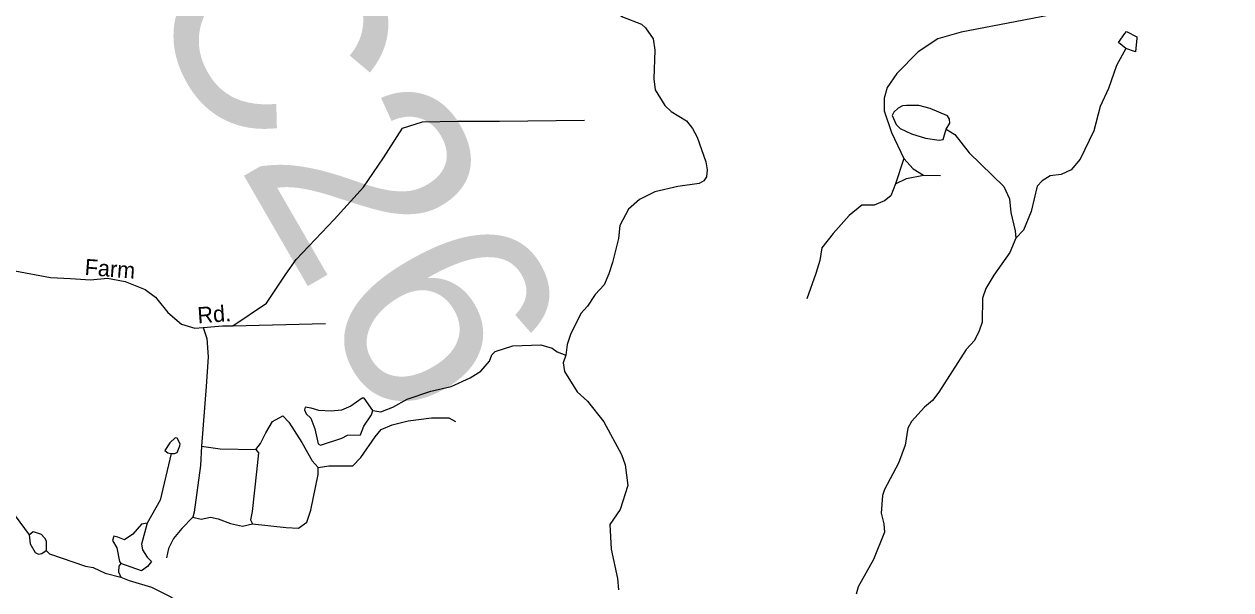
# Model space of a CAD drawing. Extents: x 2056842 to 2160602, y 826753 to 1016856.
# Drawn here: x 2076838 to 2083927, y 935892 to 939218 of the extents above; entities that cross this region are included whole.
import ezdxf

# ---------------------------------------------------------------- set-up
doc = ezdxf.new("R2010")
doc.units = 0
for name, color, linetype in [('Exist Hydrographic Creek Single Shore', 7, 'Continuous'), ('Exist Hydrographic Misc Water Feature', 7, 'Continuous'), ('Exist Hydrographic Pond Under 1500 Sq Ft', 7, 'Continuous'), ('Exist Road Non-System Type 51', 7, 'Continuous'), ('Exist Road Non-System Type 51 Label', 7, 'Continuous'), ('Exist Road Secondary Structure Culvert Number Label', 7, 'Continuous')]:
    doc.layers.add(name, color=color, linetype=linetype)

msp = doc.modelspace()

# ---------------------------------------------------------------- linework, layer by layer
at = {"layer": 'Exist Hydrographic Creek Single Shore'}
for points in [[(2079723.1, 939643.1), (2079767.4, 939627.4), (2080061.8, 939456.2), (2080258.3, 939326.8), (2080352.4, 939261.2), (2080464.4, 939217.5)], [(2080464.4, 939217.5), (2080488.5, 939195.7), (2080532.8, 939131.8), (2080542.9, 939063.6), (2080537.4, 938895.7), (2080545.6, 938831.9), (2080602.1, 938739.9), (2080640.1, 938704), (2080730.2, 938648.3), (2080764.4, 938604.6), (2080792.5, 938552.5), (2080843, 938408.7), (2080851.2, 938360.6), (2080847.4, 938320.7), (2080831.5, 938296.7), (2080803.6, 938280.5), (2080677.5, 938262.2), (2080543.7, 938231.8), (2080453.8, 938187.4), (2080388, 938129.4), (2080338.1, 938033.3), (2080330.6, 937957.3), (2080294.9, 937816.9), (2080273.1, 937749.1), (2080245.2, 937684.7), (2080193.5, 937628.7), (2080147.8, 937560.4), (2080107.8, 937516.3), (2080048.2, 937392.2), (2080028.6, 937334.2), (2080020.7, 937272.3)], [(2083311.1, 939074.6), (2083255.3, 938974.4), (2083207.6, 938838.2), (2083160, 938734.1), (2083122.5, 938590), (2083041.1, 938423.7), (2082989.2, 938361.6), (2082929.3, 938333.4), (2082865.3, 938325.2), (2082819.4, 938297), (2082789.5, 938265), (2082754, 938116.9), (2082708.3, 938006.8), (2082664.6, 937958.6)], [(2082254.5, 938599.3), (2082304.7, 938569.4), (2082389, 938461.8), (2082593.6, 938262.4), (2082625.8, 938190.5), (2082634, 938110.5), (2082660.5, 938002.7), (2082664.6, 937958.6)], [(2082664.6, 937958.6), (2082628.7, 937874.5), (2082535.2, 937742.2), (2082487.4, 937664), (2082467.7, 937606.1), (2082466.1, 937466), (2082448.3, 937414), (2082420.4, 937357.9), (2082372.6, 937305.7), (2082211.2, 937053.3), (2082173.5, 937005.2), (2082127.8, 936965), (2082051.9, 936880.8), (2082030, 936842.7), (2082014.4, 936742.6), (2081974.6, 936636.5), (2081893.2, 936482.3), (2081881.3, 936446.2), (2081873.5, 936342.2), (2081887.9, 936280.2), (2081892, 936230.3), (2081828.4, 936070), (2081736.9, 935909.8), (2081725, 935865.8)], [(2080020.7, 937272.3), (2080004.7, 937226.1), (2080012.8, 937176), (2080087.5, 937056.4), (2080147.3, 937000.6), (2080243.9, 936878.9), (2080346.6, 936687.4), (2080368.6, 936627.2), (2080384.4, 936504.5), (2080339.5, 936363.4), (2080279.6, 936275), (2080286.1, 936131.2), (2080324.6, 935959.1), (2080329.1, 935891.4)]]:
    msp.add_lwpolyline(points, dxfattribs=at)
at = {"layer": 'Exist Hydrographic Misc Water Feature'}
for points in [[(2082022.2, 938738.6), (2081998.2, 938736.4), (2081972.1, 938724.4), (2081946.3, 938700.3), (2081938.3, 938680.3), (2081960.4, 938628.4), (2081984.6, 938604.4), (2082050.7, 938572.7)], [(2082254.5, 938599.3), (2082276.4, 938635.3), (2082274.4, 938659.3), (2082262.3, 938679.3), (2082160.2, 938721), (2082094.1, 938738.8), (2082022.2, 938738.6)], [(2082050.7, 938572.7), (2082132.7, 938547), (2082212.9, 938535.2), (2082236.6, 938539.3), (2082254.5, 938599.3)], [(2078885.9, 936946.8), (2078933.9, 936938.9), (2079003.8, 936965.2), (2079087.7, 937013.5), (2079227.5, 937059.9), (2079347.5, 937088.2), (2079459.2, 937138.7), (2079521.1, 937176.8), (2079571, 937237), (2079584.9, 937273), (2079604.8, 937293.1), (2079708.8, 937325.4), (2079872.6, 937331.8), (2079940.7, 937312.1), (2079968.8, 937290.2), (2080020.9, 937272.4)], [(2078885.9, 936946.8), (2078835.7, 937018.7), (2078823.8, 937018.6), (2078757.7, 936972.4), (2078702, 936948.3), (2078641.9, 936942), (2078569.9, 936945.8), (2078524, 936959.8)], [(2078524, 936959.8), (2078489.7, 936965.6), (2078486, 936949.6), (2078494, 936925.6), (2078522.1, 936901.6), (2078546.3, 936837.8), (2078564.6, 936749.9), (2078578.5, 936741.9), (2078704.4, 936784.3)], [(2078704.4, 936784.3), (2078738.3, 936800.3), (2078814.3, 936802.6), (2078834.2, 936854.7), (2078877.9, 936920.8), (2078885.9, 936946.8)], [(2077700.9, 936693.2), (2077637.5, 936418.9), (2077560, 936284.7)], [(2076605.5, 936415.5), (2076637.5, 936407.7), (2076665.7, 936391.7), (2076713.8, 936383.8), (2076785.7, 936326.2), (2076868.1, 936214.5)], [(2077560, 936284.7), (2077528.4, 936160.7), (2077532.5, 936126.6), (2077560.6, 936084.7), (2077586.7, 936058.9), (2077562.9, 936028.7), (2077527, 936002.7), (2077406.9, 936046.3)], [(2077560, 936284.7), (2077528, 936278.6), (2077476.4, 936218.5), (2077428.4, 936186.3)], [(2077428.4, 936186.3), (2077388.4, 936202.2), (2077364.4, 936208), (2077356.4, 936182.1), (2077382.7, 936138.1), (2077398.9, 936058.2), (2077406.9, 936046.3)], [(2076966.6, 936122.6), (2076986.5, 936102.8), (2077198.7, 936031.5), (2077242.8, 936023.7), (2077314.9, 935989.7), (2077407, 935966.1)], [(2077406.9, 936046.3), (2077394.8, 936030.2), (2077392.9, 935998.2), (2077407.1, 935966.3)], [(2077407, 935966.1), (2077454.8, 935946.1), (2077587.2, 935906.6), (2077699.3, 935851.1), (2077741.3, 935823), (2077773.4, 935789.2)]]:
    msp.add_lwpolyline(points, dxfattribs=at)
at = {"layer": 'Exist Hydrographic Pond Under 1500 Sq Ft'}
for points in [[(2083304.5, 939162.5), (2083314.6, 939174.5), (2083374.7, 939142.7), (2083374.5, 939134.5)], [(2083310.9, 939074.5), (2083266.7, 939110.1), (2083304.5, 939162.5)], [(2083374.5, 939134.5), (2083366.9, 939054.6), (2083310.9, 939074.5)], [(2077694.4, 936756.9), (2077664.6, 936710.9), (2077682.7, 936697.1), (2077700.6, 936693.1)], [(2077754.3, 936751), (2077736.3, 936783.2), (2077726.2, 936785.1), (2077694.4, 936756.9)], [(2077700.6, 936693.1), (2077720.7, 936693), (2077736.5, 936699.2), (2077752.5, 936739.3), (2077754.3, 936751)], [(2076868.1, 936214.5), (2076892.1, 936234.4), (2076938.1, 936218.7), (2076958.3, 936198.5)], [(2076868.1, 936214.5), (2076874.2, 936162.6), (2076902.3, 936110.5), (2076922.5, 936102.5), (2076942.6, 936104.7), (2076966.6, 936122.6)], [(2076958.3, 936198.5), (2076968.1, 936180.6), (2076966.6, 936122.6)]]:
    msp.add_lwpolyline(points, dxfattribs=at)
at = {"layer": 'Exist Road Non-System Type 51'}
for p, q in [((2082005.4, 938427.7), (2081957.5, 938278.9)), ((2082120.6, 938330.1), (2082221.3, 938328.5)), ((2078064, 937444), (2078608.1, 937458.3))]:
    msp.add_line(p, q, dxfattribs=at)
for points in [[(2083927.2, 939746.2), (2083794, 939657), (2083493.4, 939492.2), (2083339.9, 939399.4), (2083206.2, 939341), (2083035.1, 939304.2), (2082710.5, 939240.1), (2082343.5, 939170.5), (2082206, 939130.5), (2082090.9, 939055.3), (2081964.5, 938927.3), (2081908.6, 938844.1), (2081891.1, 938782.1), (2081891.1, 938706.9), (2081932.7, 938580.5), (2082005.4, 938427.7)], [(2078064, 937444), (2078261.6, 937576.9), (2078374.7, 937747.6), (2078436.6, 937834.8), (2078659.3, 938068.4), (2078831.7, 938258.9), (2078949.3, 938432.3), (2079060.7, 938606.6), (2079177.4, 938642.5), (2079383.9, 938647.9), (2079629.9, 938646.1), (2080130, 938652.4)], [(2082005.4, 938427.7), (2082061.4, 938366.9), (2082120.6, 938330.1)], [(2081957.5, 938278.9), (2082021.4, 938310.9), (2082120.6, 938330.1)], [(2081957.5, 938278.9), (2081930.3, 938208.4), (2081891.9, 938178), (2081831.1, 938154), (2081759.2, 938154), (2081684, 938093.2), (2081590.5, 937986.8), (2081523.3, 937902), (2081512.1, 937828.4), (2081488.1, 937751.6), (2081435.4, 937602.8)], [(2075893.7, 937496.4), (2075990.8, 937563.5), (2076208.1, 937716.2), (2076328.4, 937775.5), (2076424.5, 937790.8), (2076587.9, 937794.4), (2076783.7, 937767.4), (2076993.8, 937727.9), (2077109.6, 937721.6), (2077228.1, 937714.4), (2077326.9, 937723.4), (2077431, 937705.4), (2077549.5, 937656.9), (2077610.6, 937612), (2077682.4, 937522.1), (2077763.2, 937453.8), (2077841.3, 937429.6), (2077889.8, 937435)], [(2077889.8, 937435), (2077911.4, 937370.3), (2077918.6, 937262.5), (2077907.8, 937086.4), (2077880, 936736.8)], [(2077889.8, 937435), (2078003, 937444), (2078064, 937444)], [(2078199.6, 936717.1), (2078226.5, 936751.2), (2078258.9, 936814.1), (2078296.6, 936880.6), (2078357.6, 936914.7), (2078393.5, 936877), (2078469, 936758.4), (2078530, 936650.6), (2078565.9, 936611.1)], [(2078565.9, 936611.1), (2078627.9, 936620.9), (2078769.7, 936620.9), (2078816.4, 936669.5), (2078900.8, 936791.7), (2078935, 936834.8), (2078999.6, 936861.7), (2079093.9, 936886), (2079230.4, 936902.2), (2079332.7, 936902.2), (2079372.2, 936882.4)], [(2077880, 936736.8), (2077874.6, 936623.6), (2077836.9, 936348.7), (2077829.7, 936319.9)], [(2077880, 936736.8), (2077989.5, 936720.7), (2078199.6, 936717.1)], [(2078199.6, 936717.1), (2078214.9, 936698.2), (2078204.1, 936585), (2078177.2, 936353.2), (2078168.2, 936302.9), (2078179, 936279.5)], [(2078179, 936279.5), (2078376.5, 936257.9), (2078450.1, 936254.4), (2078498.6, 936290.3), (2078521.9, 936360.4), (2078565, 936570.6), (2078565.9, 936611.1)], [(2077829.7, 936319.9), (2077765, 936251.7), (2077716.5, 936194.2), (2077686, 936134.9), (2077675.2, 936080.9)], [(2077829.7, 936319.9), (2077878.2, 936307.4), (2077932, 936319.9), (2077978.7, 936309.2), (2078050.6, 936282.2), (2078120.6, 936266), (2078179, 936279.5)]]:
    msp.add_lwpolyline(points, dxfattribs=at)

# ---------------------------------------------------------------- texts
at = {"layer": 'Exist Road Non-System Type 51 Label'}
for s, rotation, p in [('Farm', 355.71533, (2077191.4, 937743.2)), ('Rd.', 3.97851, (2077859.3, 937458.2))]:
    msp.add_text(s, height=95, rotation=rotation, dxfattribs=at).set_placement(p)
at = {"layer": 'Exist Road Secondary Structure Culvert Number Label'}
msp.add_text('C26', height=1230.31, rotation=300, dxfattribs=at).set_placement((2077494.1, 939426.9))

doc.saveas('drawing.dxf')
